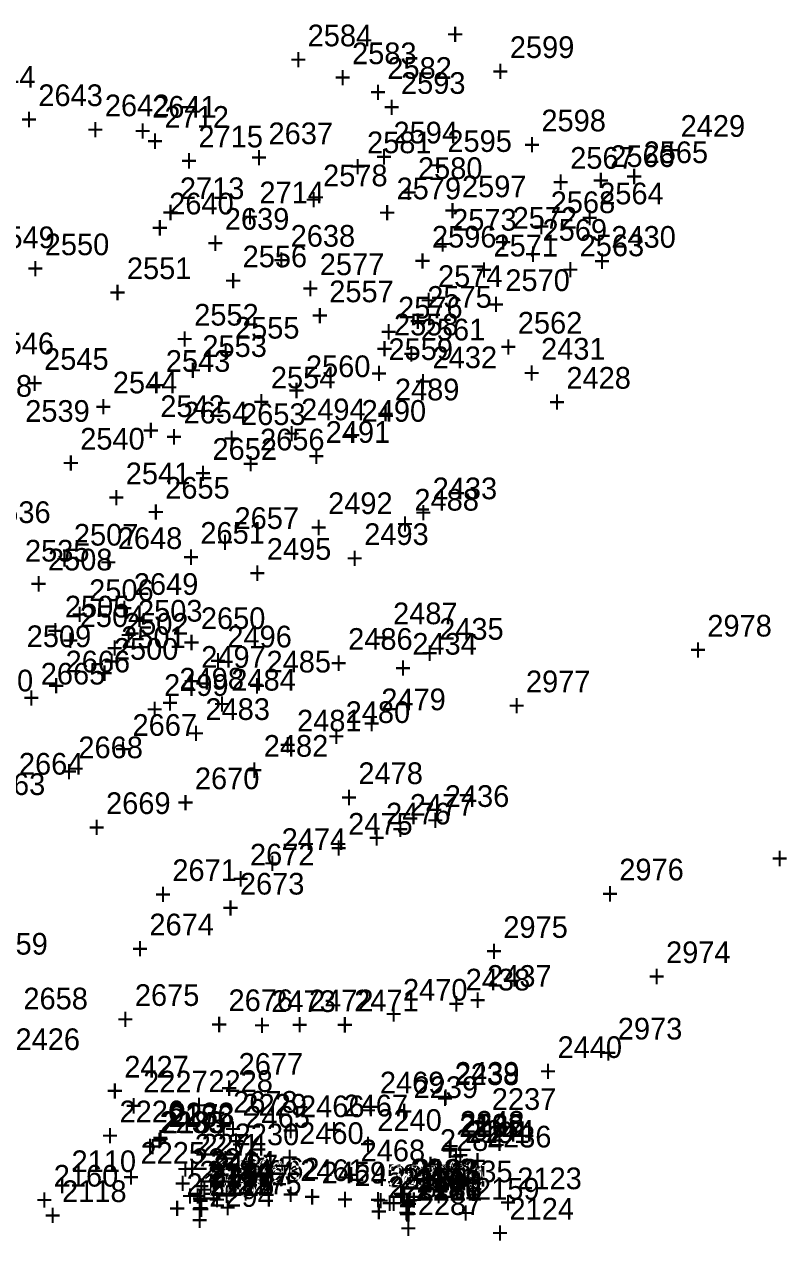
# Model space of a CAD drawing. Extents: x 2192192 to 2193475, y 863716 to 864270.
# Drawn here: x 2192641.5 to 2192729.4, y 863938.7 to 864078.8 of the extents above; entities that cross this region are included whole.
import ezdxf

# ---------------------------------------------------------------- set-up
doc = ezdxf.new("R2010")
doc.units = 0
for name, color, linetype in [('S_Bridge_Abutment_Bottom', 7, 'Continuous'), ('S_Bridge_Curb', 7, 'Continuous'), ('S_Bridge_Deck', 7, 'Continuous'), ('S_Bridge_Fascia', 7, 'Continuous'), ('S_Bridge_Parapet', 7, 'Continuous'), ('S_Bridge_Seat', 7, 'Continuous'), ('S_Bridge_Wingwall', 7, 'Continuous'), ('S_Drainage_RipRap', 7, 'Continuous'), ('S_Drainage_Waterway', 7, 'Continuous'), ('S_Ground_Elevation', 7, 'Continuous'), ('S_Ground_LevelString', 7, 'Continuous'), ('S_Ground_SpotElevation', 7, 'Continuous'), ('S_Guardrail_Beam', 7, 'Continuous'), ('S_Misc_MiscItems', 7, 'Continuous'), ('S_Roadway_Edge_Pavement', 7, 'Continuous'), ('S_Roadway_Edge_TW', 7, 'Continuous'), ('S_Trees_TreeLine', 7, 'Continuous')]:
    doc.layers.add(name, color=color, linetype=linetype)

msp = doc.modelspace()

# ---------------------------------------------------------------- texts
at = {"layer": 'S_Bridge_Abutment_Bottom'}
for s, p in [('2273', (2192658.26, 863951.91)), ('2285', (2192691.67, 863950.76)), ('+', (2192656.2, 863949.16)), ('2274', (2192661.9, 863948.46)), ('2284', (2192689.38, 863948.99)), ('+', (2192689.61, 863948.01)), ('2283', (2192686.1, 863945.52)), ('+', (2192687.32, 863946.24)), ('+', (2192659.84, 863945.71)), ('2275', (2192666, 863944)), ('2282', (2192683.42, 863943.55)), ('+', (2192684.04, 863942.77)), ('+', (2192663.94, 863941.25)), ('+', (2192681.36, 863940.8))]:
    msp.add_text(s, height=2.5, dxfattribs=at).set_placement(p)
at = {"layer": 'S_Bridge_Curb'}
for s, p in [('2221', (2192662.95, 863943.81)), ('2220', (2192686.72, 863943.27)), ('+', (2192660.89, 863941.06)), ('+', (2192684.66, 863940.52))]:
    msp.add_text(s, height=2.5, dxfattribs=at).set_placement(p)
at = {"layer": 'S_Bridge_Deck'}
for s, p in [('2215', (2192662.86, 863943.83)), ('2216', (2192686.69, 863943.26)), ('+', (2192660.8, 863941.08)), ('+', (2192684.63, 863940.51))]:
    msp.add_text(s, height=2.5, dxfattribs=at).set_placement(p)
at = {"layer": 'S_Bridge_Fascia'}
for s, p in [('2296', (2192662.85, 863944.83)), ('2297', (2192662.87, 863944.82)), ('2298', (2192686.71, 863944.27)), ('2299', (2192686.73, 863944.28)), ('+', (2192660.79, 863942.08)), ('+', (2192660.81, 863942.07)), ('+', (2192684.67, 863941.53)), ('+', (2192684.65, 863941.52))]:
    msp.add_text(s, height=2.5, dxfattribs=at).set_placement(p)
at = {"layer": 'S_Bridge_Parapet'}
for s, p in [('2179', (2192662.86, 863944.79)), ('2178', (2192662.86, 863943.94)), ('2180', (2192686.67, 863944.18)), ('2181', (2192686.61, 863943.42)), ('+', (2192660.8, 863942.04)), ('+', (2192660.8, 863941.19)), ('+', (2192684.55, 863940.67)), ('+', (2192684.61, 863941.43))]:
    msp.add_text(s, height=2.5, dxfattribs=at).set_placement(p)
at = {"layer": 'S_Bridge_Seat'}
for s, p in [('2197', (2192664.75, 863944.92)), ('2194', (2192684.66, 863944.51)), ('+', (2192662.69, 863942.17)), ('+', (2192682.6, 863941.76))]:
    msp.add_text(s, height=2.5, dxfattribs=at).set_placement(p)
at = {"layer": 'S_Bridge_Wingwall'}
for s, p in [('2185', (2192657.35, 863951.03)), ('2186', (2192658.11, 863951.74)), ('2192', (2192691.61, 863950.59)), ('2191', (2192692.31, 863949.89)), ('+', (2192656.05, 863948.99)), ('+', (2192655.29, 863948.28)), ('+', (2192689.55, 863947.84)), ('+', (2192690.25, 863947.14)), ('2184', (2192662.54, 863945.35)), ('2187', (2192663.3, 863946.06)), ('2193', (2192686.34, 863945.56)), ('2183', (2192662.81, 863945.05)), ('2182', (2192664.38, 863945.04)), ('2188', (2192685.12, 863944.51)), ('2189', (2192686.66, 863944.57)), ('2190', (2192686.99, 863944.83)), ('+', (2192661.24, 863943.32)), ('+', (2192660.48, 863942.6)), ('+', (2192660.75, 863942.3)), ('+', (2192662.32, 863942.29)), ('+', (2192683.06, 863941.76)), ('+', (2192684.28, 863942.81)), ('+', (2192684.6, 863941.82)), ('+', (2192684.93, 863942.08))]:
    msp.add_text(s, height=2.5, dxfattribs=at).set_placement(p)
at = {"layer": 'S_Drainage_RipRap'}
for s, p in [('2238', (2192691.07, 863956.58)), ('2227', (2192655.17, 863955.73)), ('2228', (2192662.69, 863955.79)), ('2239', (2192686.34, 863955.08)), ('2237', (2192695.36, 863953.72)), ('+', (2192653.11, 863952.98)), ('+', (2192660.63, 863953.04)), ('2229', (2192666.61, 863953.06)), ('+', (2192689, 863953.83)), ('2226', (2192652.44, 863952.29)), ('2233', (2192657.05, 863951.05)), ('2232', (2192658.22, 863952.05)), ('2240', (2192682.16, 863951.3)), ('+', (2192684.28, 863952.33)), ('2243', (2192691.7, 863951.09)), ('+', (2192664.55, 863950.31)), ('2230', (2192665.72, 863949.65)), ('2244', (2192692.81, 863950.04)), ('+', (2192693.3, 863950.97)), ('+', (2192650.37, 863949.54)), ('+', (2192656.16, 863949.3)), ('2231', (2192661.12, 863948.45)), ('+', (2192680.1, 863948.55)), ('2236', (2192694.8, 863949.39)), ('2225', (2192654.86, 863947.52)), ('+', (2192654.98, 863948.3)), ('2224', (2192660.81, 863946.79)), ('+', (2192689.64, 863948.34)), ('+', (2192690.75, 863947.29)), ('+', (2192663.66, 863946.9)), ('2242', (2192685.99, 863945.59)), ('2235', (2192690.32, 863945.38)), ('+', (2192692.74, 863946.64)), ('+', (2192652.8, 863944.77)), ('+', (2192659.05, 863945.7)), ('2241', (2192683.63, 863944.8)), ('2234', (2192687.47, 863944.88)), ('+', (2192658.75, 863944.04)), ('+', (2192681.57, 863942.05)), ('+', (2192683.93, 863942.84)), ('+', (2192685.4, 863942.13)), ('+', (2192688.26, 863942.63))]:
    msp.add_text(s, height=2.5, dxfattribs=at).set_placement(p)
at = {"layer": 'S_Drainage_Waterway'}
for s, p in [('2644', (2192635.31, 864071.49)), ('2582', (2192683.32, 864072.52)), ('+', (2192681.26, 864069.77)), ('2641', (2192656.2, 864068.05)), ('+', (2192654.14, 864065.3)), ('2637', (2192669.62, 864064.99)), ('2581', (2192680.98, 864063.95)), ('+', (2192667.56, 864062.24)), ('2567', (2192704.4, 864062.16)), ('2565', (2192712.86, 864062.81)), ('+', (2192678.92, 864061.2)), ('2580', (2192686.85, 864060.98)), ('+', (2192702.34, 864059.41)), ('+', (2192710.8, 864060.06)), ('+', (2192684.79, 864058.23)), ('2564', (2192707.74, 864058.06)), ('2640', (2192658.17, 864056.9)), ('2568', (2192702.15, 864057.05)), ('2639', (2192664.58, 864055.13)), ('2573', (2192690.79, 864055.03)), ('2572', (2192697.76, 864055.25)), ('+', (2192705.68, 864055.31)), ('+', (2192656.11, 864054.15)), ('+', (2192700.09, 864054.3)), ('2549', (2192637.54, 864053.01)), ('+', (2192662.52, 864052.38)), ('2638', (2192672.17, 864053.18)), ('+', (2192688.73, 864052.28)), ('+', (2192695.7, 864052.5)), ('2563', (2192705.49, 864052.08)), ('+', (2192670.11, 864050.43)), ('2574', (2192689.16, 864048.54)), ('+', (2192703.43, 864049.33)), ('+', (2192687.1, 864045.79)), ('2561', (2192687.17, 864042.38)), ('2562', (2192698.36, 864043.17)), ('2546', (2192637.46, 864040.78)), ('2553', (2192661.99, 864040.48)), ('+', (2192685.11, 864039.63)), ('+', (2192696.3, 864040.42)), ('2543', (2192657.78, 864038.76)), ('+', (2192659.92, 864037.73)), ('2554', (2192669.89, 864036.86)), ('2538', (2192634.92, 864035.89)), ('+', (2192655.71, 864036.01)), ('2489', (2192684.19, 864035.47)), ('+', (2192667.82, 864034.11)), ('2542', (2192657.14, 864033.55)), ('2494', (2192673.38, 864033.18)), ('+', (2192682.13, 864032.72)), ('+', (2192655.08, 864030.8)), ('+', (2192671.32, 864030.43)), ('2541', (2192653.16, 864025.81)), ('+', (2192651.1, 864023.06)), ('2488', (2192686.44, 864022.77)), ('+', (2192684.38, 864020.02)), ('2507', (2192647.18, 864018.74)), ('2495', (2192669.42, 864017.1)), ('+', (2192645.12, 864015.99)), ('+', (2192667.36, 864014.35)), ('2506', (2192648.94, 864012.35)), ('2505', (2192646.14, 864010.46)), ('2503', (2192654.57, 864009.98)), ('+', (2192646.87, 864009.6)), ('2487', (2192683.98, 864009.68)), ('2509', (2192641.74, 864007.04)), ('+', (2192644.08, 864007.71)), ('2496', (2192664.87, 864007.01)), ('2500', (2192651.79, 864005.58)), ('+', (2192652.51, 864007.23)), ('+', (2192681.92, 864006.93)), ('+', (2192662.81, 864004.26)), ('2510', (2192635.05, 864001.94)), ('+', (2192649.73, 864002.83)), ('2499', (2192657.58, 864001.42)), ('2483', (2192662.35, 863998.65)), ('2479', (2192682.62, 863999.77)), ('+', (2192655.52, 863998.67)), ('+', (2192680.55, 863997.02)), ('+', (2192660.29, 863995.9)), ('2482', (2192669.07, 863994.41)), ('+', (2192667, 863991.66)), ('2477', (2192685.91, 863987.61)), ('2474', (2192671.13, 863983.67)), ('+', (2192683.85, 863984.86)), ('+', (2192669.07, 863980.92)), ('2470', (2192685.12, 863966.31)), ('2473', (2192669.94, 863965)), ('+', (2192683.06, 863963.56)), ('+', (2192667.88, 863962.25)), ('2469', (2192682.46, 863955.62)), ('+', (2192680.4, 863952.87)), ('2465', (2192666.95, 863951.66)), ('+', (2192664.89, 863948.91)), ('2468', (2192680.24, 863947.79)), ('2464', (2192662.95, 863946.47)), ('2463', (2192665.88, 863945.41)), ('+', (2192678.17, 863945.04)), ('2457', (2192683.34, 863944.91)), ('+', (2192660.89, 863943.72)), ('+', (2192663.82, 863942.66)), ('+', (2192681.28, 863942.16))]:
    msp.add_text(s, height=2.5, dxfattribs=at).set_placement(p)
at = {"layer": 'S_Ground_Elevation'}
for s, p in [('+', (2192690.16, 864076.44)), ('2599', (2192697.44, 864074.92)), ('+', (2192695.38, 864072.17)), ('2593', (2192684.89, 864070.79)), ('+', (2192682.83, 864068.04)), ('2712', (2192657.62, 864066.88)), ('2598', (2192701.08, 864066.47)), ('2429', (2192717.13, 864065.84)), ('2715', (2192661.54, 864064.62)), ('2594', (2192684.03, 864065.08)), ('+', (2192655.55, 864064.13)), ('2595', (2192690.24, 864064.1)), ('+', (2192699.02, 864063.72)), ('+', (2192681.97, 864062.33)), ('+', (2192715.07, 864063.09)), ('+', (2192659.48, 864061.87)), ('+', (2192688.18, 864061.35)), ('2597', (2192691.92, 864058.88)), ('2713', (2192659.4, 864058.66)), ('2714', (2192668.57, 864058.18)), ('+', (2192657.34, 864055.91)), ('+', (2192666.51, 864055.43)), ('+', (2192689.86, 864056.13)), ('2596', (2192688.46, 864053.08)), ('2430', (2192709.14, 864053.06)), ('+', (2192686.4, 864050.33)), ('+', (2192707.08, 864050.31)), ('2432', (2192688.53, 864039.18)), ('2431', (2192701.04, 864040.17)), ('+', (2192698.97, 864037.42)), ('+', (2192686.46, 864036.43)), ('2654', (2192659.82, 864032.81)), ('2653', (2192666.45, 864032.63)), ('+', (2192657.75, 864030.06)), ('+', (2192664.39, 864029.88)), ('2656', (2192668.64, 864029.71)), ('2652', (2192663.16, 864028.62)), ('+', (2192661.1, 864025.87)), ('+', (2192666.58, 864026.96)), ('2655', (2192657.71, 864024.15)), ('2433', (2192688.54, 864024.08)), ('+', (2192655.65, 864021.4)), ('2657', (2192665.7, 864020.66)), ('+', (2192686.48, 864021.33)), ('2648', (2192652.24, 864018.35)), ('2651', (2192661.76, 864018.95)), ('+', (2192663.64, 864017.91)), ('+', (2192659.7, 864016.2)), ('+', (2192650.18, 864015.6)), ('2649', (2192654.09, 864013.06)), ('+', (2192652.03, 864010.31)), ('2650', (2192661.82, 864009.12)), ('2978', (2192720.21, 864008.26)), ('+', (2192659.76, 864006.37)), ('2434', (2192686.2, 864006.17)), ('+', (2192718.15, 864005.51)), ('2666', (2192646.22, 864004.13)), ('+', (2192684.14, 864003.42)), ('2665', (2192643.36, 864002.73)), ('2977', (2192699.3, 864001.84)), ('+', (2192644.16, 864001.38)), ('+', (2192641.3, 863999.98)), ('+', (2192697.24, 863999.09)), ('2667', (2192653.94, 863996.82)), ('+', (2192651.88, 863994.07)), ('2664', (2192640.84, 863992.35)), ('2670', (2192661.13, 863990.67)), ('2663', (2192636.44, 863990)), ('+', (2192659.07, 863987.92)), ('2436', (2192689.94, 863988.63)), ('+', (2192687.88, 863985.88)), ('2672', (2192667.48, 863981.88)), ('+', (2192727.57, 863981.48)), ('2976', (2192710.06, 863980.16)), ('+', (2192665.42, 863979.13)), ('2673', (2192666.32, 863978.53)), ('+', (2192708, 863977.41)), ('+', (2192664.26, 863975.78)), ('2975', (2192696.69, 863973.54)), ('2659', (2192636.74, 863971.61)), ('+', (2192694.63, 863970.79)), ('2438', (2192692.35, 863967.48)), ('2658', (2192641.36, 863965.3)), ('2676', (2192665.01, 863965.1)), ('+', (2192690.29, 863964.73)), ('+', (2192662.95, 863962.35)), ('2973', (2192709.89, 863961.83)), ('2426', (2192640.45, 863960.61)), ('+', (2192707.83, 863959.08)), ('2427', (2192652.99, 863957.45)), ('2677', (2192666.17, 863957.77)), ('2439', (2192691.12, 863956.73)), ('+', (2192650.93, 863954.7)), ('+', (2192664.11, 863955.02)), ('2678', (2192665.54, 863953.39)), ('+', (2192689.06, 863953.98)), ('+', (2192663.48, 863950.64))]:
    msp.add_text(s, height=2.5, dxfattribs=at).set_placement(p)
at = {"layer": 'S_Ground_LevelString'}
for s, p in [('2113', (2192660.17, 863943.91)), ('2294', (2192662.78, 863942.55)), ('2295', (2192662.81, 863943.86)), ('2286', (2192686.79, 863943.35)), ('2287', (2192686.82, 863941.61)), ('+', (2192658.11, 863941.16)), ('+', (2192660.75, 863941.11)), ('+', (2192684.73, 863940.6)), ('+', (2192660.71, 863939.8)), ('+', (2192684.76, 863938.86))]:
    msp.add_text(s, height=2.5, dxfattribs=at).set_placement(p)
at = {"layer": 'S_Ground_SpotElevation'}
for s, p in [('2584', (2192674.13, 864076.27)), ('+', (2192672.07, 864073.52)), ('2583', (2192679.25, 864074.21)), ('+', (2192677.19, 864071.46)), ('2643', (2192643.08, 864069.38)), ('2642', (2192650.75, 864068.21)), ('+', (2192641.02, 864066.63)), ('+', (2192648.69, 864065.46)), ('2566', (2192709.02, 864062.36)), ('2578', (2192675.91, 864060.14)), ('+', (2192706.96, 864059.61)), ('2579', (2192684.38, 864058.64)), ('+', (2192673.85, 864057.39)), ('+', (2192682.32, 864055.89)), ('2569', (2192701.21, 864053.86)), ('2550', (2192643.82, 864052.2)), ('2571', (2192695.56, 864052.05)), ('2556', (2192666.63, 864050.81)), ('+', (2192699.15, 864051.11)), ('+', (2192641.76, 864049.45)), ('2551', (2192653.29, 864049.44)), ('2577', (2192675.53, 864049.9)), ('+', (2192664.57, 864048.06)), ('+', (2192693.5, 864049.3)), ('2570', (2192696.92, 864048.07)), ('+', (2192651.23, 864046.69)), ('+', (2192673.47, 864047.15)), ('2557', (2192676.62, 864046.78)), ('2576', (2192684.56, 864044.91)), ('2575', (2192687.92, 864046.14)), ('+', (2192694.86, 864045.32)), ('2552', (2192661.05, 864044.09)), ('+', (2192674.56, 864044.03)), ('2555', (2192665.75, 864042.59)), ('2558', (2192684.08, 864042.96)), ('+', (2192685.86, 864043.39)), ('+', (2192658.99, 864041.34)), ('+', (2192682.5, 864042.16)), ('+', (2192663.69, 864039.84)), ('+', (2192682.02, 864040.21)), ('2545', (2192643.75, 864038.99)), ('+', (2192641.69, 864036.24)), ('2544', (2192651.67, 864036.28)), ('2539', (2192641.57, 864033)), ('+', (2192649.61, 864033.53)), ('2490', (2192680.35, 864033.01)), ('2540', (2192647.91, 864029.8)), ('2491', (2192676.21, 864030.58)), ('+', (2192678.29, 864030.26)), ('+', (2192645.85, 864027.05)), ('+', (2192674.15, 864027.83)), ('2492', (2192676.49, 864022.37)), ('2536', (2192637.06, 864021.34)), ('+', (2192674.43, 864019.62)), ('2493', (2192680.65, 864018.81)), ('2535', (2192641.54, 864016.9)), ('2508', (2192644.19, 864015.88)), ('+', (2192678.59, 864016.06)), ('+', (2192642.13, 864013.13)), ('2504', (2192647.86, 864009.36)), ('2502', (2192652.96, 864008.47)), ('+', (2192645.8, 864006.61)), ('2501', (2192652.63, 864006.93)), ('2486', (2192678.8, 864006.73)), ('+', (2192650.9, 864005.72)), ('2497', (2192661.86, 864004.66)), ('+', (2192650.57, 864004.18)), ('2485', (2192669.39, 864004.12)), ('+', (2192676.74, 864003.98)), ('2498', (2192659.35, 864002.15)), ('+', (2192659.8, 864001.91)), ('2484', (2192665.33, 864002.03)), ('+', (2192667.32, 864001.37)), ('+', (2192657.28, 863999.4)), ('+', (2192663.27, 863999.28)), ('2481', (2192672.91, 863997.32)), ('2480', (2192678.51, 863998.3)), ('+', (2192676.45, 863995.55)), ('2668', (2192647.7, 863994.24)), ('+', (2192670.85, 863994.57)), ('+', (2192645.64, 863991.49)), ('2478', (2192679.98, 863991.26)), ('2669', (2192650.89, 863987.81)), ('+', (2192677.91, 863988.51)), ('2476', (2192683.17, 863986.61)), ('+', (2192648.82, 863985.06)), ('2475', (2192678.8, 863985.43)), ('+', (2192681.11, 863983.86)), ('+', (2192676.73, 863982.68)), ('2671', (2192658.53, 863980.09)), ('+', (2192656.47, 863977.34)), ('2674', (2192655.89, 863973.83)), ('+', (2192653.83, 863971.08)), ('2974', (2192715.45, 863970.63)), ('+', (2192713.39, 863967.88)), ('2675', (2192654.21, 863965.7)), ('2472', (2192674.29, 863965.07)), ('2471', (2192679.5, 863965.06)), ('+', (2192652.14, 863962.95)), ('+', (2192672.23, 863962.32)), ('+', (2192677.44, 863962.31)), ('2466', (2192673.25, 863952.88)), ('2467', (2192678.26, 863952.97)), ('+', (2192671.19, 863950.13)), ('2460', (2192673.15, 863949.79)), ('+', (2192676.19, 863950.22)), ('2462', (2192668.07, 863945.7)), ('+', (2192671.09, 863947.04)), ('2461', (2192673.27, 863945.52)), ('2459', (2192675.74, 863945.24)), ('2458', (2192679.53, 863944.94)), ('+', (2192666.01, 863942.95)), ('+', (2192671.21, 863942.77)), ('+', (2192673.68, 863942.49)), ('+', (2192677.47, 863942.19))]:
    msp.add_text(s, height=2.5, dxfattribs=at).set_placement(p)
at = {"layer": 'S_Guardrail_Beam'}
for s, p in [('2160', (2192644.86, 863944.88)), ('2159', (2192693.43, 863943.38)), ('+', (2192642.8, 863942.13)), ('+', (2192691.37, 863940.63))]:
    msp.add_text(s, height=2.5, dxfattribs=at).set_placement(p)
at = {"layer": 'S_Misc_MiscItems'}
for s, p in [('2559', (2192683.45, 864040.12)), ('2560', (2192673.93, 864038.15)), ('+', (2192681.38, 864037.37)), ('+', (2192671.87, 864035.4))]:
    msp.add_text(s, height=2.5, dxfattribs=at).set_placement(p)
at = {"layer": 'S_Roadway_Edge_Pavement'}
for s, p in [('2110', (2192646.91, 863946.55)), ('2111', (2192661.65, 863945.34)), ('2122', (2192686.89, 863944.45)), ('2123', (2192698.3, 863944.58)), ('+', (2192644.85, 863943.8)), ('2112', (2192662.76, 863943.83)), ('2121', (2192686.85, 863943.26)), ('+', (2192659.59, 863942.59)), ('+', (2192684.82, 863941.7)), ('+', (2192696.24, 863941.83)), ('+', (2192660.7, 863941.08)), ('+', (2192684.79, 863940.52))]:
    msp.add_text(s, height=2.5, dxfattribs=at).set_placement(p)
at = {"layer": 'S_Roadway_Edge_TW'}
for s, p in [('2118', (2192645.82, 863943.1)), ('2124', (2192697.4, 863941.08)), ('+', (2192643.76, 863940.35)), ('+', (2192695.34, 863938.33))]:
    msp.add_text(s, height=2.5, dxfattribs=at).set_placement(p)
at = {"layer": 'S_Trees_TreeLine'}
for s, p in [('2428', (2192703.96, 864036.82)), ('+', (2192701.9, 864034.07)), ('2435', (2192689.29, 864007.89)), ('+', (2192687.23, 864005.14)), ('2437', (2192694.82, 863967.9)), ('+', (2192692.76, 863965.15)), ('2440', (2192702.94, 863959.7)), ('+', (2192700.87, 863956.95))]:
    msp.add_text(s, height=2.5, dxfattribs=at).set_placement(p)

doc.saveas('drawing.dxf')
